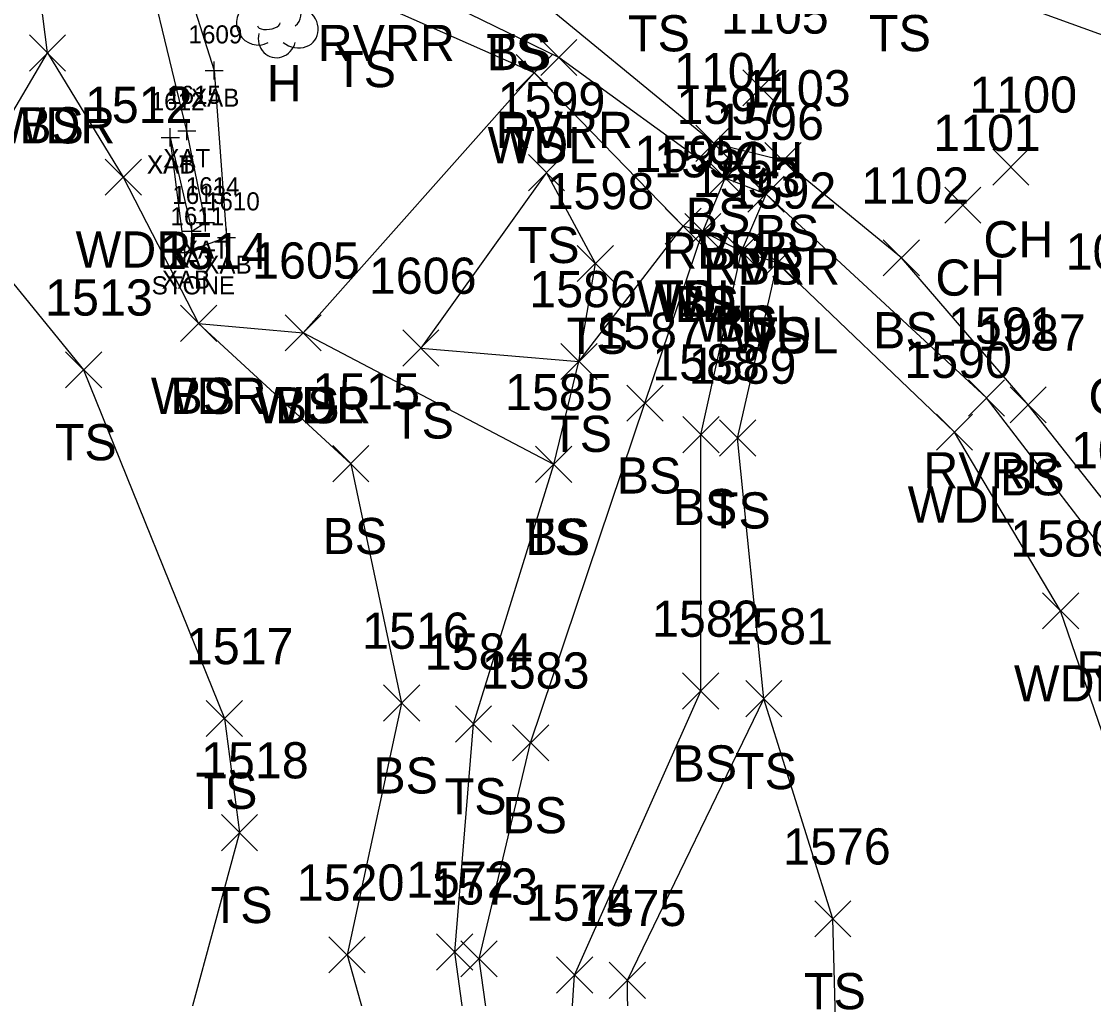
# Model space of a CAD drawing. Extents: x 1600281 to 1602254, y 862855 to 863227.
# Drawn here: x 1602047.3 to 1602106.5, y 862978.2 to 863032.2 of the extents above; entities that cross this region are included whole.
import ezdxf

# ---------------------------------------------------------------- set-up
doc = ezdxf.new("R2010")
doc.units = 0
for name, color, linetype in [('B_A', 7, 'Continuous'), ('B_C', 7, 'Continuous'), ('B_I', 7, 'Continuous'), ('B_TIC', 7, 'Continuous'), ('BSUBM', 7, 'Continuous'), ('L_A', 7, 'Continuous'), ('L_I', 7, 'Continuous'), ('L_TIC', 7, 'Continuous'), ('LAWA', 7, 'Continuous'), ('LAWE', 7, 'Continuous'), ('LELB', 7, 'Continuous'), ('LTD', 7, 'Continuous')]:
    doc.layers.add(name, color=color, linetype=linetype)

msp = doc.modelspace()

# ---------------------------------------------------------------- linework, layer by layer
at = {"layer": 'B_TIC'}
for p, q in [((1602057.933, 863029.474), (1602058.008, 863029.474)), ((1602056.422, 863026.134), (1602056.497, 863026.134)), ((1602055.515, 863025.783), (1602055.591, 863025.783)), ((1602055.515, 863025.783), (1602055.591, 863025.783)), ((1602057.451, 863021.08), (1602057.527, 863021.08)), ((1602056.712, 863020.601), (1602056.787, 863020.601)), ((1602058.614, 863020.244), (1602058.69, 863020.244)), ((1602056.325, 863019.422), (1602056.401, 863019.422))]:
    msp.add_line(p, q, dxfattribs=at)
for points in [[(1602057.929, 863028.974), (1602057.929, 863029.974)], [(1602057.429, 863029.474), (1602058.429, 863029.474)], [(1602056.418, 863025.634), (1602056.418, 863026.634)], [(1602055.512, 863025.283), (1602055.512, 863026.283)], [(1602055.512, 863025.283), (1602055.512, 863026.283)], [(1602055.918, 863026.134), (1602056.918, 863026.134)], [(1602055.012, 863025.783), (1602056.012, 863025.783)], [(1602055.012, 863025.783), (1602056.012, 863025.783)], [(1602057.448, 863020.58), (1602057.448, 863021.58)], [(1602056.708, 863020.101), (1602056.708, 863021.101)], [(1602056.948, 863021.08), (1602057.948, 863021.08)], [(1602058.611, 863019.744), (1602058.611, 863020.744)], [(1602056.208, 863020.601), (1602057.208, 863020.601)], [(1602058.111, 863020.244), (1602059.111, 863020.244)], [(1602056.322, 863018.922), (1602056.322, 863019.922)], [(1602055.822, 863019.422), (1602056.822, 863019.422)]]:
    msp.add_lwpolyline(points, dxfattribs=at)
at = {"layer": 'BSUBM'}
for points in [[(1602055.512, 863025.783), (1602056.708, 863020.601), (1602057.448, 863021.08), (1602056.418, 863026.134), (1602053.452, 863038.428), (1602051.655, 863043.876), (1602033.283, 863054.61)], [(1602052.338, 863044.601), (1602054.868, 863040.585), (1602055.206, 863038.057), (1602057.929, 863029.474), (1602058.611, 863020.244), (1602056.322, 863019.422), (1602055.512, 863025.783)]]:
    msp.add_lwpolyline(points, dxfattribs=at)
at = {"layer": 'L_TIC'}
for points in [[(1602047.724, 863029.448), (1602049.724, 863031.448)], [(1602049.724, 863029.448), (1602047.724, 863031.448)], [(1602047.724, 863029.448), (1602049.724, 863031.448)], [(1602049.724, 863029.448), (1602047.724, 863031.448)], [(1602075.977, 863029.193), (1602077.977, 863031.193)], [(1602077.977, 863029.193), (1602075.977, 863031.193)], [(1602074.62, 863028.355), (1602076.62, 863030.355)], [(1602076.62, 863028.355), (1602074.62, 863030.355)], [(1602074.62, 863028.355), (1602076.62, 863030.355)], [(1602076.62, 863028.355), (1602074.62, 863030.355)], [(1602087.137, 863027.517), (1602089.137, 863029.517)], [(1602089.137, 863027.517), (1602087.137, 863029.517)], [(1602084.541, 863024.448), (1602086.541, 863026.448)], [(1602086.541, 863024.448), (1602084.541, 863026.448)], [(1602088.354, 863023.498), (1602090.354, 863025.498)], [(1602090.354, 863023.498), (1602088.354, 863025.498)], [(1602075.295, 863022.834), (1602077.295, 863024.834)], [(1602077.295, 863022.834), (1602075.295, 863024.834)], [(1602100.944, 863023.146), (1602102.944, 863025.146)], [(1602102.944, 863023.146), (1602100.944, 863025.146)], [(1602051.915, 863022.582), (1602053.915, 863024.582)], [(1602053.915, 863022.582), (1602051.915, 863024.582)], [(1602085.169, 863022.524), (1602087.169, 863024.524)], [(1602087.169, 863022.524), (1602085.169, 863024.524)], [(1602085.169, 863022.524), (1602087.169, 863024.524)], [(1602087.169, 863022.524), (1602085.169, 863024.524)], [(1602087.422, 863021.641), (1602089.422, 863023.641)], [(1602089.422, 863021.641), (1602087.422, 863023.641)], [(1602087.422, 863021.641), (1602089.422, 863023.641)], [(1602089.422, 863021.641), (1602087.422, 863023.641)], [(1602098.293, 863021.031), (1602100.293, 863023.031)], [(1602100.293, 863021.031), (1602098.293, 863023.031)], [(1602082.846, 863019.871), (1602084.846, 863021.871)], [(1602084.846, 863019.871), (1602082.846, 863021.871)], [(1602082.846, 863019.871), (1602084.846, 863021.871)], [(1602084.846, 863019.871), (1602082.846, 863021.871)], [(1602083.93, 863019.571), (1602085.93, 863021.571)], [(1602085.93, 863019.571), (1602083.93, 863021.571)], [(1602083.93, 863019.571), (1602085.93, 863021.571)], [(1602085.93, 863019.571), (1602083.93, 863021.571)], [(1602086.063, 863018.481), (1602088.063, 863020.481)], [(1602088.063, 863018.481), (1602086.063, 863020.481)], [(1602086.063, 863018.481), (1602088.063, 863020.481)], [(1602088.063, 863018.481), (1602086.063, 863020.481)], [(1602094.897, 863018.119), (1602096.897, 863020.119)], [(1602096.897, 863018.119), (1602094.897, 863020.119)], [(1602077.993, 863017.813), (1602079.993, 863019.813)], [(1602079.993, 863017.813), (1602077.993, 863019.813)], [(1602088.047, 863017.841), (1602090.047, 863019.841)], [(1602090.047, 863017.841), (1602088.047, 863019.841)], [(1602088.047, 863017.841), (1602090.047, 863019.841)], [(1602090.047, 863017.841), (1602088.047, 863019.841)], [(1602056.074, 863014.497), (1602058.074, 863016.497)], [(1602058.074, 863014.497), (1602056.074, 863016.497)], [(1602056.074, 863014.497), (1602058.074, 863016.497)], [(1602058.074, 863014.497), (1602056.074, 863016.497)], [(1602061.849, 863013.974), (1602063.849, 863015.974)], [(1602063.849, 863013.974), (1602061.849, 863015.974)], [(1602061.849, 863013.974), (1602063.849, 863015.974)], [(1602063.849, 863013.974), (1602061.849, 863015.974)], [(1602061.849, 863013.974), (1602063.849, 863015.974)], [(1602063.849, 863013.974), (1602061.849, 863015.974)], [(1602068.354, 863013.133), (1602070.354, 863015.133)], [(1602070.354, 863013.133), (1602068.354, 863015.133)], [(1602077.086, 863012.394), (1602079.086, 863014.394)], [(1602079.086, 863012.394), (1602077.086, 863014.394)], [(1602077.086, 863012.394), (1602079.086, 863014.394)], [(1602079.086, 863012.394), (1602077.086, 863014.394)], [(1602049.721, 863011.929), (1602051.721, 863013.929)], [(1602051.721, 863011.929), (1602049.721, 863013.929)], [(1602099.599, 863010.379), (1602101.599, 863012.379)], [(1602101.599, 863010.379), (1602099.599, 863012.379)], [(1602080.733, 863010.092), (1602082.733, 863012.092)], [(1602082.733, 863010.092), (1602080.733, 863012.092)], [(1602101.906, 863009.993), (1602103.906, 863011.993)], [(1602103.906, 863009.993), (1602101.906, 863011.993)], [(1602083.825, 863008.345), (1602085.825, 863010.345)], [(1602085.825, 863008.345), (1602083.825, 863010.345)], [(1602085.854, 863008.161), (1602087.854, 863010.161)], [(1602087.854, 863008.161), (1602085.854, 863010.161)], [(1602097.833, 863008.484), (1602099.833, 863010.484)], [(1602099.833, 863008.484), (1602097.833, 863010.484)], [(1602064.481, 863006.744), (1602066.481, 863008.744)], [(1602066.481, 863006.744), (1602064.481, 863008.744)], [(1602075.694, 863006.703), (1602077.694, 863008.703)], [(1602077.694, 863006.703), (1602075.694, 863008.703)], [(1602075.694, 863006.703), (1602077.694, 863008.703)], [(1602077.694, 863006.703), (1602075.694, 863008.703)], [(1602103.696, 862998.605), (1602105.696, 863000.605)], [(1602105.696, 862998.605), (1602103.696, 863000.605)], [(1602083.814, 862994.174), (1602085.814, 862996.174)], [(1602085.814, 862994.174), (1602083.814, 862996.174)], [(1602067.287, 862993.511), (1602069.287, 862995.511)], [(1602069.287, 862993.511), (1602067.287, 862995.511)], [(1602087.297, 862993.751), (1602089.297, 862995.751)], [(1602089.297, 862993.751), (1602087.297, 862995.751)], [(1602087.297, 862993.751), (1602089.297, 862995.751)], [(1602089.297, 862993.751), (1602087.297, 862995.751)], [(1602057.497, 862992.658), (1602059.497, 862994.658)], [(1602059.497, 862992.658), (1602057.497, 862994.658)], [(1602071.263, 862992.358), (1602073.263, 862994.358)], [(1602073.263, 862992.358), (1602071.263, 862994.358)], [(1602074.414, 862991.31), (1602076.414, 862993.31)], [(1602076.414, 862991.31), (1602074.414, 862993.31)], [(1602058.334, 862986.347), (1602060.334, 862988.347)], [(1602060.334, 862986.347), (1602058.334, 862988.347)], [(1602091.109, 862981.585), (1602093.109, 862983.585)], [(1602093.109, 862981.585), (1602091.109, 862983.585)], [(1602064.274, 862979.593), (1602066.274, 862981.593)], [(1602066.274, 862979.593), (1602064.274, 862981.593)], [(1602070.226, 862979.749), (1602072.226, 862981.749)], [(1602072.226, 862979.749), (1602070.226, 862981.749)], [(1602071.569, 862979.371), (1602073.569, 862981.371)], [(1602073.569, 862979.371), (1602071.569, 862981.371)], [(1602076.845, 862978.478), (1602078.845, 862980.478)], [(1602078.845, 862978.478), (1602076.845, 862980.478)], [(1602079.76, 862978.184), (1602081.76, 862980.184)], [(1602081.76, 862978.184), (1602079.76, 862980.184)]]:
    msp.add_lwpolyline(points, dxfattribs=at)
at = {"layer": 'LAWA'}
for points in [[(1602013.88, 862864.604), (1602012.852, 862879.286), (1602012.389, 862885.249), (1602013.668, 862890.426), (1602013.993, 862891.89), (1602014.423, 862895.34), (1602031.133, 862915.343), (1602041.823, 862936.999), (1602041.484, 862949.365), (1602043.119, 862970.368), (1602043.104, 862998.4), (1602042.776, 863006.718), (1602043.565, 863021.702), (1602048.724, 863030.448), (1602052.915, 863023.582), (1602057.074, 863015.497), (1602062.849, 863014.974)], [(1602096.406, 862879.641), (1602095.369, 862902.033), (1602099.326, 862919.262), (1602109.634, 862945.957), (1602110.967, 862962.959), (1602110.328, 862983.187), (1602104.696, 862999.605), (1602098.833, 863009.484), (1602089.047, 863018.841), (1602087.063, 863019.481), (1602084.93, 863020.571), (1602083.846, 863020.871), (1602075.62, 863029.355), (1602062.849, 863014.974)]]:
    msp.add_lwpolyline(points, dxfattribs=at)
at = {"layer": 'LAWE'}
msp.add_lwpolyline([(1602098.435, 862879.183), (1602097.38, 862900.93), (1602100.821, 862918.119), (1602111.897, 862945.191), (1602113.655, 862964.279), (1602114.598, 862983.415), (1602109.052, 863000.365), (1602100.599, 863011.379), (1602088.422, 863022.641), (1602086.169, 863023.524), (1602076.977, 863030.193), (1602067.142, 863034.999), (1602054.868, 863040.585)], dxfattribs=at)
at = {"layer": 'LELB'}
for points in [[(1602099.842, 862878.347), (1602100.95, 862904.784), (1602110.589, 862929.642), (1602115.654, 862954.701), (1602118.276, 862973.935), (1602116.239, 862983.386), (1602108.039, 863004.489), (1602102.906, 863010.993), (1602095.897, 863019.119), (1602089.354, 863024.498), (1602085.541, 863025.448), (1602074.55, 863034.496), (1602069.632, 863039.23), (1602052.338, 863044.601)], [(1602048.724, 863030.448), (1602047.849, 863037.414), (1602046.402, 863038.482)], [(1602075.62, 863029.355), (1602066.153, 863033.557), (1602055.206, 863038.057)], [(1602116.925, 863005.507), (1602113.863, 863021.47), (1602110.735, 863030.077), (1602095.702, 863035.545), (1602082.388, 863035.535), (1602074.55, 863034.496)], [(1602078.086, 863013.394), (1602078.993, 863018.813), (1602076.295, 863023.834), (1602069.354, 863014.133)], [(1601758.874, 862935.581), (1601794.57, 862931.041), (1601823.257, 862926.647), (1601871.558, 862921.026), (1601900.015, 862918.494), (1601930.467, 862913.509), (1601956.156, 862906.35), (1601972.874, 862902.678), (1601993.622, 862897.851), (1602007.259, 862890.971), (1602013.993, 862891.89), (1602036.738, 862896.625), (1602039.12, 862902.94), (1602042.648, 862913.223), (1602071.455, 862922.172), (1602077.729, 862924.942), (1602082.998, 862929.527), (1602079.846, 862943.099), (1602074.854, 862964.036), (1602072.569, 862980.371), (1602075.414, 862992.31), (1602081.733, 863011.092), (1602084.93, 863020.571), (1602086.169, 863023.524)], [(1601758.252, 862932.382), (1601793.251, 862926.874), (1601822.781, 862921.72), (1601870.875, 862915.198), (1601899.959, 862912.838), (1601929.995, 862911.268), (1601955.114, 862904.27), (1601972.397, 862900.453), (1601993.867, 862895.104), (1602006.953, 862889.055), (1602013.668, 862890.426), (1602037.377, 862895.193), (1602041.453, 862902.138), (1602044.339, 862911.825), (1602073.391, 862917.1), (1602080.565, 862918.061), (1602084.273, 862928.901), (1602082.101, 862942.173), (1602076.793, 862963.57), (1602077.845, 862979.478), (1602084.814, 862995.174), (1602084.825, 863009.345), (1602087.063, 863019.481), (1602088.422, 863022.641)], [(1602043.565, 863021.702), (1602050.721, 863012.929), (1602058.497, 862993.658), (1602059.334, 862987.347), (1602055.31, 862972.472), (1602061.28, 862961.826)], [(1601758.889, 862937.881), (1601795.072, 862933.903), (1601823.846, 862928.868), (1601870.343, 862922.924), (1601900.351, 862921.152), (1601930.516, 862914.56), (1601956.196, 862907.256), (1601973.319, 862904.611), (1601993.849, 862899.996), (1602008.191, 862895.024), (1602014.423, 862895.34), (1602035.615, 862898.845), (1602036.447, 862903.94), (1602042.391, 862916.03), (1602070.541, 862924.323), (1602075.868, 862928.131), (1602081.563, 862930.038), (1602078.855, 862942.657), (1602073.583, 862963.521), (1602071.226, 862980.749), (1602072.263, 862993.358), (1602076.694, 863007.703), (1602078.086, 863013.394), (1602083.846, 863020.871)], [(1601994.69, 862890.807), (1602005.018, 862886.613), (1602012.389, 862885.249), (1602036.932, 862893.166), (1602042.387, 862901.65), (1602044.794, 862907.826), (1602074.596, 862913.524), (1602080.814, 862915.532), (1602085.28, 862928.211), (1602083.535, 862943.154), (1602080.901, 862962.87), (1602080.76, 862979.184), (1602088.297, 862994.751), (1602086.854, 863009.161), (1602089.047, 863018.841)], [(1602057.074, 863015.497), (1602065.481, 863007.744), (1602068.287, 862994.511), (1602065.274, 862980.593), (1602070.089, 862963.456), (1602072.28, 862941.969)], [(1602076.694, 863007.703), (1602062.849, 863014.974)], [(1602069.354, 863014.133), (1602078.086, 863013.394)], [(1602099.326, 862919.262), (1602093.331, 862945.837), (1602092.628, 862963.103), (1602092.109, 862982.585), (1602088.297, 862994.751)]]:
    msp.add_lwpolyline(points, dxfattribs=at)
at = {"layer": 'LTD'}
for centre, major_axis, ratio, start_param, end_param in [((1602060.325, 863032.065), (0.584, -1.042), 0.959034, 3.141593, 6.283185), ((1602061.908, 863032.607), (-0.5, 0.667), 0.989748, 3.141593, 6.283185), ((1602062.408, 863031.94), (-1.09, 0.792), 0.841452, 1.570796, 4.712389), ((1602060.95, 863032.024), (-0.625, -0.083), 0.423636, 0, 3.141593), ((1602061.408, 863031.274), (0.265, 1.061), 0.942809, 1.570796, 4.712389)]:
    msp.add_ellipse(centre, major_axis=major_axis, ratio=ratio, start_param=start_param, end_param=end_param, dxfattribs=at)

# ---------------------------------------------------------------- texts
at = {"layer": 'B_A'}
for s, p in [('XAB', (1602056.65, 863027.474)), ('XAT', (1602055.123, 863024.134)), ('XAT', (1602054.216, 863023.783)), ('XAB', (1602054.232, 863023.783)), ('XAT', (1602056.152, 863019.08)), ('XAT', (1602055.413, 863018.601)), ('XAB', (1602057.331, 863018.244)), ('XAB', (1602055.042, 863017.422))]:
    msp.add_text(s, height=1, dxfattribs=at).set_placement(p)
at = {"layer": 'B_C'}
msp.add_text('STONE', height=1, dxfattribs=at).set_placement((1602054.48, 863017.101))
at = {"layer": 'B_I'}
for s, p in [('1609', (1602056.516, 863030.974)), ('1615', (1602055.331, 863027.634)), ('1612', (1602054.425, 863027.283)), ('1612', (1602054.425, 863027.283)), ('1613', (1602055.621, 863022.101)), ('1614', (1602056.361, 863022.58)), ('1610', (1602057.481, 863021.744)), ('1611', (1602055.519, 863020.922))]:
    msp.add_text(s, height=1, dxfattribs=at).set_placement(p)
at = {"layer": 'L_A'}
for s, p in [('TS', (1602080.798, 863030.535)), ('TS', (1602094.112, 863030.545)), ('RVRR', (1602063.654, 863029.999)), ('TS', (1602072.959, 863029.496)), ('BS', (1602072.991, 863029.496)), ('TS', (1602064.563, 863028.557)), ('H', (1602060.841, 863027.774)), ('WDR', (1602046.086, 863025.448)), ('BS', (1602047.165, 863025.448)), ('RVRR', (1602073.489, 863025.193)), ('WDL', (1602073.037, 863024.355)), ('TS', (1602074.03, 863024.355)), ('CH', (1602086.625, 863023.517)), ('BS', (1602083.981, 863020.448)), ('BS', (1602087.795, 863019.498)), ('TS', (1602074.704, 863018.834)), ('CH', (1602100.432, 863019.146)), ('WDR', (1602050.278, 863018.582)), ('RVRR', (1602082.68, 863018.524)), ('BS', (1602084.61, 863018.524)), ('RVRR', (1602084.934, 863017.641)), ('BS', (1602086.863, 863017.641)), ('CH', (1602097.781, 863017.031)), ('WDL', (1602081.263, 863015.871)), ('TS', (1602082.255, 863015.871)), ('WDL', (1602082.347, 863015.571)), ('BS', (1602083.371, 863015.571)), ('WDL', (1602084.48, 863014.481)), ('BS', (1602085.504, 863014.481)), ('BS', (1602094.338, 863014.119)), ('TS', (1602077.402, 863013.813)), ('WDL', (1602086.464, 863013.841)), ('TS', (1602087.457, 863013.841)), ('WDR', (1602054.436, 863010.497)), ('BS', (1602055.515, 863010.497)), ('CH', (1602106.235, 863010.477)), ('WDR', (1602060.211, 863009.974)), ('WDL', (1602060.266, 863009.974)), ('BS', (1602061.29, 863009.974)), ('TS', (1602067.763, 863009.133)), ('TS', (1602076.496, 863008.394)), ('TS', (1602076.496, 863008.394)), ('TS', (1602049.13, 863007.929)), ('RVRR', (1602097.111, 863006.379)), ('BS', (1602080.174, 863006.092)), ('BS', (1602101.347, 863005.993)), ('WDL', (1602096.25, 863004.484)), ('BS', (1602083.266, 863004.345)), ('TS', (1602085.264, 863004.161)), ('BS', (1602063.921, 863002.744)), ('TS', (1602075.104, 863002.703)), ('BS', (1602075.135, 863002.703)), ('RVRR', (1602105.563, 862995.365)), ('WDL', (1602102.114, 862994.605)), ('BS', (1602083.255, 862990.174)), ('TS', (1602086.706, 862989.751)), ('TS', (1602086.706, 862989.751)), ('BS', (1602066.728, 862989.511)), ('TS', (1602056.906, 862988.658)), ('TS', (1602070.672, 862988.358)), ('BS', (1602073.855, 862987.31)), ('TS', (1602057.744, 862982.347)), ('TS', (1602090.518, 862977.585))]:
    msp.add_text(s, height=2, dxfattribs=at).set_placement(p)
at = {"layer": 'L_I'}
for s, p in [('1105', (1602085.933, 863031.517)), ('1104', (1602083.336, 863028.448)), ('1103', (1602087.149, 863027.498)), ('1100', (1602099.653, 863027.146)), ('1512', (1602050.79, 863026.582)), ('1599', (1602073.594, 863026.834)), ('1597', (1602083.476, 863026.524)), ('1597', (1602083.476, 863026.524)), ('1596', (1602085.674, 863025.641)), ('1596', (1602085.674, 863025.641)), ('1101', (1602097.655, 863025.031)), ('1595', (1602081.153, 863023.871)), ('1595', (1602081.153, 863023.871)), ('1594', (1602082.237, 863023.571)), ('1594', (1602082.237, 863023.571)), ('1593', (1602084.37, 863022.481)), ('1593', (1602084.37, 863022.481)), ('1598', (1602076.3, 863021.813)), ('1592', (1602086.354, 863021.841)), ('1592', (1602086.354, 863021.841)), ('1102', (1602093.692, 863022.119)), ('1514', (1602054.948, 863018.497)), ('1514', (1602054.948, 863018.497)), ('1088', (1602104.975, 863018.477)), ('1605', (1602060.03, 863017.974)), ('1605', (1602060.03, 863017.974)), ('1605', (1602060.03, 863017.974)), ('1606', (1602066.48, 863017.133)), ('1586', (1602075.338, 863016.394)), ('1586', (1602075.338, 863016.394)), ('1513', (1602048.595, 863015.929)), ('1587', (1602079.04, 863014.092)), ('1591', (1602098.473, 863014.379)), ('1087', (1602100.134, 863013.993)), ('1588', (1602082.133, 863012.345)), ('1589', (1602084.153, 863012.161)), ('1590', (1602096.054, 863012.484)), ('1515', (1602063.355, 863010.744)), ('1585', (1602074.001, 863010.703)), ('1585', (1602074.001, 863010.703)), ('1078', (1602105.268, 863007.489)), ('1580', (1602101.917, 863002.605)), ('1582', (1602082.121, 862998.174)), ('1516', (1602066.106, 862997.511)), ('1581', (1602086.171, 862997.751)), ('1581', (1602086.171, 862997.751)), ('1517', (1602056.371, 862996.658)), ('1584', (1602069.57, 862996.358)), ('1583', (1602072.721, 862995.31)), ('1518', (1602057.208, 862990.347)), ('1576', (1602089.361, 862985.585)), ('1572', (1602068.533, 862983.749)), ('1520', (1602062.494, 862983.593)), ('1573', (1602069.876, 862983.371)), ('1574', (1602075.152, 862982.478)), ('1575', (1602078.067, 862982.184))]:
    msp.add_text(s, height=2, dxfattribs=at).set_placement(p)

doc.saveas('drawing.dxf')
